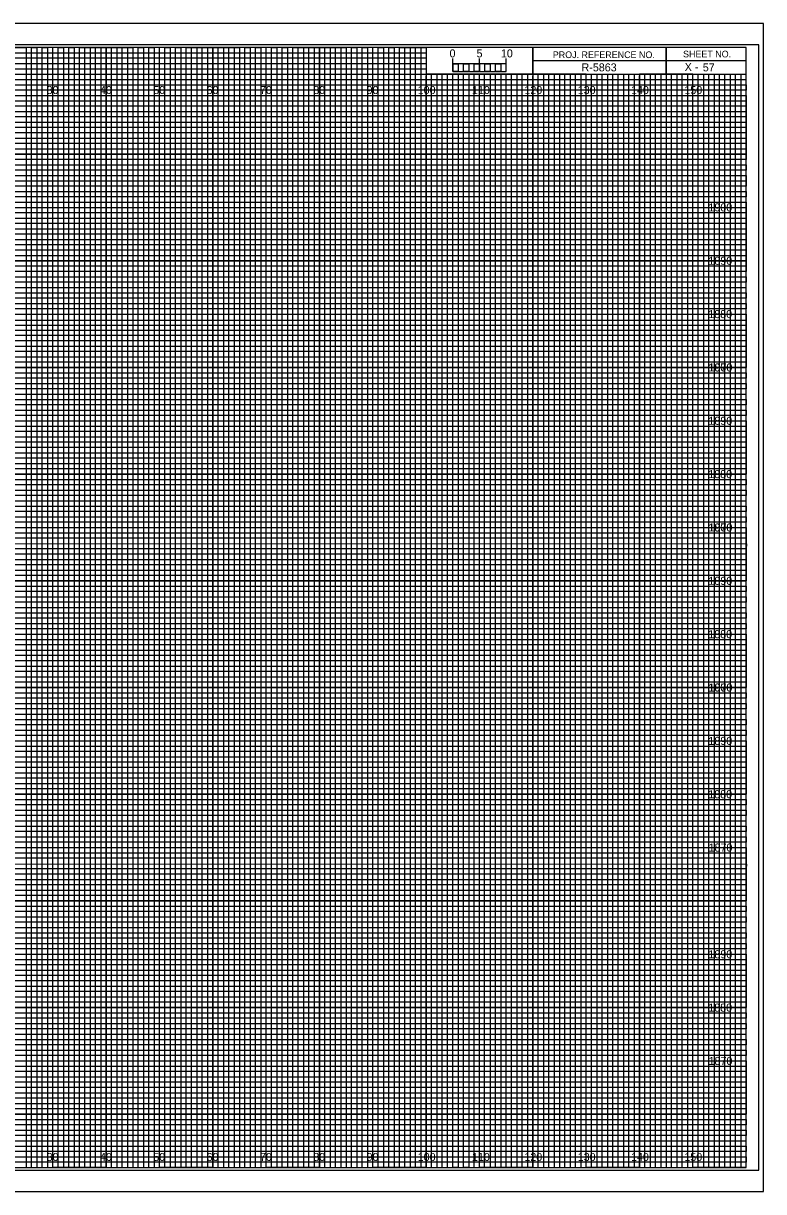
# Model space of a CAD drawing. Extents: x -13 to 323, y -4 to 214.
# Drawn here: x 184.5 to 323.3, y -4.5 to 214.5 of the extents above; entities that cross this region are included whole.
import ezdxf

# ---------------------------------------------------------------- set-up
doc = ezdxf.new("R2010")
doc.units = 0
for name, color, linetype in [('Prop XS Bar Scale Labels', 7, 'Continuous'), ('Prop XS Elevation Labels', 7, 'Continuous'), ('Prop XS Offset Labels', 7, 'Continuous'), ('Prop XS Project Number', 7, 'Continuous'), ('Prop XS Sheet Number', 7, 'Continuous'), ('Sheet Cross Section CELL', 7, 'Continuous'), ('Sheet Cross Section Grid Major CELL', 7, 'Continuous'), ('Sheet Cross Section Grid Middle CELL', 7, 'Continuous'), ('Sheet Cross Section Grid Minor 1 CELL', 7, 'Continuous'), ('Sheet Cross Section Grid Minor 2 CELL', 7, 'Continuous'), ('Sheet Cross Section Scale CELL', 7, 'Continuous'), ('Sheet Cutting Line CELL', 7, 'Continuous'), ('Sheet DOT Grid CELL', 7, 'Continuous'), ('Sheet Plot Border Inside CELL', 7, 'Continuous'), ('Sheet Plot Border Outside CELL', 7, 'Continuous')]:
    doc.layers.add(name, color=color, linetype=linetype)

msp = doc.modelspace()

# ---------------------------------------------------------------- linework, layer by layer
at = {"layer": 'Sheet Cross Section CELL'}
for p, q in [((305, 210), (305, 205)), ((305, 205), (305, 210)), ((280, 207.5), (280, 205)), ((320, 207.49), (280, 207.49)), ((280, 205), (320, 205))]:
    msp.add_line(p, q, dxfattribs=at)
for points in [[(320, 210), (0, 210), (0, 0), (320, 0)], [(280, 210), (260, 210), (260, 205.03), (280, 205.03)], [(320, 210), (280, 210), (280, 205), (320, 205)]]:
    msp.add_lwpolyline(points, close=True, dxfattribs=at)
at = {"layer": 'Sheet Cross Section Grid Major CELL'}
for p, q in [((190, 210), (180, 210)), ((190, 0), (190, 210)), ((210, 210), (200, 210)), ((200, 210), (200, 0)), ((210, 0), (210, 210)), ((230, 210), (220, 210)), ((220, 210), (220, 0)), ((230, 0), (230, 210)), ((250, 210), (240, 210)), ((240, 210), (240, 0)), ((250, 0), (250, 210)), ((260, 210), (260, 0)), ((270, 0), (270, 205)), ((290, 205), (280, 205)), ((280, 205), (280, 0)), ((290, 0), (290, 205)), ((310, 205), (300, 205)), ((300, 205), (300, 0)), ((310, 0), (310, 205)), ((200, 0), (190, 0)), ((220, 0), (210, 0)), ((240, 0), (230, 0)), ((260, 0), (250, 0)), ((280, 0), (270, 0)), ((300, 0), (290, 0)), ((320, 0), (310, 0)), ((320, 0), (320, 0))]:
    msp.add_line(p, q, dxfattribs=at)
for points in [[(0, 200), (320, 200), (320, 190), (0, 190)], [(0, 180), (320, 180), (320, 170), (0, 170)], [(0, 160), (320, 160), (320, 150), (0, 150)], [(0, 140), (320, 140), (320, 130), (0, 130)], [(0, 120), (320, 120), (320, 110), (0, 110)], [(0, 100), (320, 100), (320, 90), (0, 90)], [(0, 80), (320, 80), (320, 70), (0, 70)], [(0, 60), (320, 60), (320, 50), (0, 50)], [(0, 40), (320, 40), (320, 30), (0, 30)], [(0, 20), (320, 20), (320, 10), (0, 10)]]:
    msp.add_lwpolyline(points, dxfattribs=at)
at = {"layer": 'Sheet Cross Section Grid Middle CELL'}
for points in [[(175, 210), (185, 210), (185, 0), (195, 0), (195, 210), (205, 210), (205, 0), (215, 0), (215, 210), (225, 210), (225, 0), (235, 0), (235, 210), (245, 210), (245, 0), (255, 0), (255, 210), (259.93, 210), (260, 210), (260, 205), (264.99, 205), (264.99, 0), (275, 0), (275, 205), (285, 205), (285, 0), (295, 0), (295, 205), (305, 205), (305, 0), (315, 0), (315, 205)], [(0, 205), (275, 205)], [(0, 185), (320, 185), (320, 195), (0, 195)], [(0, 165), (320, 165), (320, 175), (0, 175)], [(0, 145), (320, 145), (320, 155), (0, 155)], [(0, 125), (320, 125), (320, 135), (0, 135)], [(0, 105), (320, 105), (320, 115), (0, 115)], [(0, 85), (320, 85), (320, 95), (0, 95)], [(0, 65), (320, 65), (320, 75), (0, 75)], [(0, 45), (320, 45), (320, 55), (0, 55)], [(0, 25), (320, 25), (320, 35), (0, 35)], [(0, 5), (320, 5), (320, 15), (0, 15)]]:
    msp.add_lwpolyline(points, dxfattribs=at)
at = {"layer": 'Sheet Cross Section Grid Minor 1 CELL'}
for p, q in [((0, 209), (260, 209)), ((260, 209), (260, 207.98)), ((260, 207.98), (0, 207.98)), ((0, 207), (260, 207)), ((260, 205.89), (0, 205.89)), ((260, 207), (260, 205.89)), ((0, 204), (320, 204))]:
    msp.add_line(p, q, dxfattribs=at)
for points in [[(0, 203), (270, 203), (320, 203), (320, 202), (0, 202)], [(0, 201), (320, 201), (320, 199), (0, 199)], [(0, 198), (320, 198), (320, 197), (0, 196.98)], [(0, 196), (320, 196), (320, 194), (0, 194)], [(0, 193), (320, 193), (320, 192), (0, 192)], [(0, 191), (320, 191), (320, 189), (0, 189)], [(0, 188), (320, 188), (320, 187), (0, 187)], [(0, 186), (320, 186), (320, 184), (0, 184)], [(0, 183), (320, 183), (320, 182), (0, 182)], [(0, 181), (320, 181), (320, 179), (0, 179)], [(0, 178), (320, 178), (320, 177), (0, 177)], [(0, 176), (320, 176), (320, 173.95), (320, 173), (320, 172), (0, 172)], [(0, 174), (320, 174), (320, 173), (0, 173)], [(0, 171), (320, 171), (320, 169), (0, 169.03)], [(0, 169.03), (320, 169), (320, 168), (0, 168)], [(0, 167), (320, 167), (320, 166), (0, 166)], [(0, 164), (320, 164), (320, 163), (0, 163)], [(0, 162), (320, 162), (320, 161), (0, 161)], [(-0.07, 158.89), (320, 158.89), (320, 157.88), (-0.07, 157.88)], [(0, 157), (320, 157), (320, 156), (0, 156)], [(0, 154), (320, 154), (320, 153), (0, 153)], [(0, 152), (320, 152), (320, 151), (0, 151)], [(0, 149), (320, 149), (320, 148), (0, 148)], [(0, 147), (320, 147), (320, 146), (0, 146)], [(0, 144), (320, 144), (320, 143), (0, 143)], [(0, 142), (320, 142), (320, 141), (0, 141)], [(0, 139), (320, 139), (319.99, 137.98), (0, 138)], [(0, 137), (320, 137), (320, 136), (0, 136)], [(0, 134), (320, 134), (320, 133), (0, 133)], [(0, 132), (320, 132), (320, 131), (0, 131)], [(0, 129), (320, 129), (320, 128), (0, 128)], [(0, 127), (320, 127), (320, 126), (0, 126)], [(0, 124), (320, 124), (320, 123), (0, 123)], [(0, 122), (320, 122), (320, 121), (0, 121)], [(0, 119), (320, 119), (320, 118), (0, 118)], [(0, 116.99), (320.07, 116.91), (320, 116), (0, 116)], [(0, 114), (320, 114), (320, 113), (0, 113)], [(0, 112), (320, 112), (320, 111), (0, 111)], [(0, 109), (320, 109), (320, 108), (0, 108)], [(0, 107), (320, 107), (320, 106), (0, 106)], [(0, 104), (320, 104), (320, 103), (0, 103)], [(0, 102), (320, 102), (320, 101), (0, 101)], [(0, 99), (320, 99), (320, 98), (0, 98)], [(0, 97), (320, 97), (320, 96), (0, 96)], [(0, 94), (320, 94), (320, 93), (0, 93)], [(0, 92), (320, 92), (320, 91), (0, 91)], [(0, 89), (320, 89), (320, 88), (0, 88)], [(0, 87), (320, 87), (320, 86), (0, 86)], [(0, 84), (320, 84), (320, 83), (0, 83)], [(0, 82), (320, 82), (320, 81), (0, 81)], [(0, 79), (320, 79), (319.99, 77.98), (0, 78)], [(0, 77), (320, 77), (320, 76), (0, 76)], [(0, 74), (320, 74), (320, 73), (0, 73)], [(0, 72), (320, 72), (320, 71), (0, 71)], [(0, 69), (320, 69), (320, 68), (0, 68)], [(0, 67), (320, 67), (320, 66), (0, 66)], [(0, 64), (320, 64), (320, 63), (0, 63)], [(0, 62), (320, 62), (320, 61), (0, 61)], [(0, 59), (320, 59), (320, 58), (0, 58)], [(0, 56.99), (320.07, 56.91), (320, 56), (0, 56)], [(0, 54), (320, 54), (320, 53), (0, 53)], [(0, 52), (320, 52), (320, 51), (0, 51)], [(0, 49), (320, 49), (320, 48), (0, 48)], [(0, 47), (320, 47), (320, 46), (0, 46)], [(0, 44), (320, 44), (320, 43), (0, 43)], [(0, 42), (320, 42), (320, 41), (0, 41)], [(0, 39), (320, 39), (320, 38), (0, 38)], [(0, 37), (320, 37), (320, 36), (0, 36)], [(0, 34), (320, 34), (320, 33), (0, 33)], [(0, 32), (320, 32), (320, 31), (0, 31)], [(0, 29), (320, 29), (320, 28), (0, 28)], [(0, 27), (320, 27), (320, 26), (0, 26)], [(0, 24), (320, 24), (320, 23), (0, 23)], [(0, 22), (320, 22), (320, 21), (0, 21)], [(0, 19), (320, 19), (320, 18), (0, 18)], [(0, 17), (320, 17), (320, 16), (0, 16)], [(0, 14), (320, 14), (320, 13), (0, 13)], [(0, 12), (320, 12), (320, 11), (0, 11)], [(0, 9), (320, 9), (320, 8), (0, 8)], [(0, 7), (320, 7), (320, 6), (0, 6)], [(0, 4), (320, 4), (320, 3), (0, 3)], [(0, 2), (320, 2), (320, 1), (0, 1)]]:
    msp.add_lwpolyline(points, dxfattribs=at)
at = {"layer": 'Sheet Cross Section Grid Minor 2 CELL'}
for p, q in [((267, 205), (266.01, 205)), ((266.01, 205), (266.01, 0)), ((267, 0), (267, 205)), ((269, 205), (268, 205)), ((268, 205), (268, 0)), ((269, 0), (269, 205)), ((266.01, 0), (265, 0)), ((268, 0), (267, 0))]:
    msp.add_line(p, q, dxfattribs=at)
for points in [[(185, 0), (186, 0), (186, 210), (187, 210), (187, 0)], [(187, 0), (188, 0), (188, 210), (189, 210), (189, 0)], [(190, 0), (191, 0), (191, 210), (192, 210), (192, 0)], [(192, 0), (193, 0), (193, 210), (194, 210), (194, 0)], [(195, 0), (196, 0), (196, 210), (197, 210), (197, 0)], [(197, 0), (198, 0), (198, 210), (199, 210), (199, 0)], [(200, 0), (201, 0), (201, 210), (202, 210), (202, 0)], [(202, 0), (203, 0), (203, 210), (204, 210), (204, 0)], [(205, 0), (206, 0), (206, 210), (207, 210), (207, 0)], [(207, 0), (208, 0), (208, 210), (209, 210), (209, 0)], [(210, 0), (211, 0), (211, 210), (212, 210), (212, 0)], [(212, 0), (213, 0), (213, 210), (214, 210), (214, 0)], [(215, 0), (216, 0), (216, 210), (217, 210), (217, 0)], [(217, 0), (218, 0), (218, 210), (219, 210), (219, 0)], [(220, 0), (221, 0), (221, 210), (222, 210), (222, 0)], [(222, 0), (223, 0), (223, 210), (224, 210), (224, 0)], [(225, 0), (226, 0), (226, 210), (227, 210), (227, 0)], [(227, 0), (228, 0), (228, 210), (229, 210), (229, 0)], [(230, 0), (231, 0), (231, 210), (232, 210), (232, 0)], [(232, 0), (233, 0), (233, 210), (234, 210), (234, 0)], [(235, 0), (236, 0), (236, 210), (237, 210), (237, 0)], [(237, 0), (238, 0), (238, 210), (239, 210), (239, 0)], [(240, 0), (241, 0), (241, 210), (242, 210), (242, 0)], [(242, 0), (243, 0), (243, 210), (244, 210), (244, 0)], [(245, 0), (246, 0), (246, 210), (247, 210), (247, 0)], [(247, 0), (248, 0), (248, 210), (249, 210), (249, 0)], [(250, 0), (251, 0), (251, 210), (252, 210), (252, 0)], [(252, 0), (253, 0), (253, 210), (254, 210), (254, 0)], [(255, 0), (256, 0), (256, 210), (257, 210), (257, 0)], [(257, 0), (258, 0), (258, 210), (259, 210), (259, 0)], [(260, 0), (261, 0), (261, 205), (262.02, 205), (262.02, 0)], [(262, 0), (263, 0), (263, 205), (263.99, 205), (263.99, 0)], [(270, 0), (270.98, 0), (270.98, 205), (272, 205), (272, 0)], [(272, 0), (273, 0), (273, 205), (274.05, 205), (274.05, 0)], [(275, 0), (276, 0), (276, 205), (277, 205), (277, 0)], [(277, 0), (278, 0), (278, 205), (279, 205), (279, 0)], [(280, 0), (281, 0), (281, 205), (282, 205), (282, 0)], [(282, 0), (283, 0), (283, 205), (284, 205), (284, 0)], [(285, 0), (286, 0), (286, 205), (287, 205), (287, 0)], [(287, 0), (288, 0), (288, 205), (289, 205), (289, 0)], [(290, 0), (291, 0), (291, 205), (292, 205), (292, 0)], [(292, 0), (293, 0), (293, 205), (294, 205), (294, 0)], [(295, 0), (296, 0), (296, 205), (297, 205), (297, 0)], [(297, 0), (298, 0), (298, 205), (299, 205), (299, 0)], [(300, 0), (301, 0), (301, 205), (302, 205), (302, 0)], [(302, 0), (303, 0), (303, 205), (304, 205), (304, 0)], [(305, 0), (306, 0), (306, 205), (307, 205), (307, 0)], [(307, 0), (308, 0), (308, 205), (309, 205), (309, 0)], [(310, 0), (311, 0), (311, 205), (312, 205), (312, 0)], [(312, 0), (313, 0), (313, 205), (314, 205), (314, 0)], [(315, 0), (316, 0), (316, 205), (317, 205), (317, 0)], [(317, 0), (318, 0), (318, 205), (319, 205), (319, 0)]]:
    msp.add_lwpolyline(points, dxfattribs=at)
at = {"layer": 'Sheet Cross Section Scale CELL'}
for p, q in [((265, 205.49), (265, 207.9)), ((265, 206.9), (265, 207.9)), ((270, 205.49), (270, 207.9)), ((275, 205.49), (275, 207.9)), ((275, 206.9), (275, 207.9))]:
    msp.add_line(p, q, dxfattribs=at)
for points in [[(275, 206.9), (265, 206.9), (265, 205.49), (275, 205.49)], [(265, 206.9), (266, 206.9), (266, 205.49), (265, 205.49)], [(267, 206.9), (268, 206.9), (268, 205.49), (267, 205.49)], [(269, 206.9), (270, 206.9), (270, 205.49), (269, 205.49)], [(271, 206.9), (272, 206.9), (272, 205.49), (271, 205.49)], [(273, 206.9), (274, 206.9), (274, 205.49), (273, 205.49)]]:
    msp.add_lwpolyline(points, close=True, dxfattribs=at)
at = {"layer": 'Sheet Cutting Line CELL'}
for p, q in [((323.3, 214.5), (-13.4, 214.5)), ((-13.4, -4.5), (323.3, -4.5))]:
    msp.add_line(p, q, dxfattribs=at)
at = {"layer": 'Sheet DOT Grid CELL'}
for p, q in [((190, 0), (190, 210)), ((200, 0), (200, 210)), ((210, 0), (210, 210)), ((220, 0), (220, 210)), ((230, 0), (230, 210)), ((240, 0), (240, 210)), ((250, 0), (250, 210)), ((260, 0), (260, 204.69)), ((270, 0), (270, 204.69)), ((280, 0), (280, 204.69)), ((290, 0), (290, 204.69)), ((300, 0), (300, 204.69)), ((310, 0), (310, 204.69)), ((0, 200), (320, 200)), ((0, 190), (320, 190)), ((0, 180), (320, 180)), ((0, 170), (320, 170)), ((0, 160), (320, 160)), ((0, 150), (320, 150)), ((0, 140), (320, 140)), ((0, 130), (320, 130)), ((0, 120), (320, 120)), ((0, 110), (320, 110)), ((0, 100), (320, 100)), ((0, 90), (320, 90)), ((0, 80), (320, 80)), ((0, 70), (320, 70)), ((0, 60), (320, 60)), ((0, 50), (320, 50)), ((0, 40), (320, 40)), ((0, 30), (320, 30)), ((0, 20), (320, 20)), ((0, 10), (320, 10))]:
    msp.add_line(p, q, dxfattribs=at)
at = {"layer": 'Sheet Plot Border Inside CELL'}
msp.add_lwpolyline([(-10.8, -0.5), (322.4, -0.5), (322.4, 210.5), (-10.8, 210.5)], close=True, dxfattribs=at)
at = {"layer": 'Sheet Plot Border Outside CELL'}
msp.add_lwpolyline([(-13.4, -4.5), (323.3, -4.5), (323.3, 214.5), (-13.4, 214.5)], close=True, dxfattribs=at)

# ---------------------------------------------------------------- texts
at = {"layer": 'Prop XS Bar Scale Labels'}
for s, p in [('5', (269.47, 208.12)), ('10', (274.04, 208.12))]:
    msp.add_text(s, height=1.5, dxfattribs=at).set_placement(p)
at = {"layer": 'Prop XS Elevation Labels'}
for s, p in [('1900', (312.95, 179.25)), ('1890', (312.95, 169.25)), ('1880', (312.92, 159.25)), ('1900', (312.95, 149.25)), ('1870', (312.98, 149.25)), ('1890', (312.95, 139.25)), ('1880', (312.92, 129.25)), ('1900', (312.95, 119.25)), ('1870', (312.98, 119.25)), ('1890', (312.95, 109.25)), ('1880', (312.92, 99.25)), ('1900', (312.95, 89.25)), ('1870', (312.98, 89.25)), ('1890', (312.95, 79.25)), ('1880', (312.92, 69.25)), ('1870', (312.98, 59.25)), ('1890', (312.95, 39.25)), ('1880', (312.92, 29.25)), ('1870', (312.98, 19.25))]:
    msp.add_text(s, height=1.5, dxfattribs=at).set_placement(p)
at = {"layer": 'Prop XS Offset Labels'}
for s, p in [('30', (188.86, 201.25)), ('40', (198.86, 201.25)), ('50', (208.86, 201.25)), ('60', (218.86, 201.25)), ('70', (228.86, 201.25)), ('80', (238.86, 201.25)), ('90', (248.86, 201.25)), ('100', (258.44, 201.25)), ('110', (268.62, 201.25)), ('120', (278.44, 201.25)), ('130', (288.44, 201.25)), ('140', (298.44, 201.25)), ('150', (308.44, 201.25)), ('30', (188.86, 1.25)), ('40', (198.86, 1.25)), ('50', (208.86, 1.25)), ('60', (218.86, 1.25)), ('70', (228.86, 1.25)), ('80', (238.86, 1.25)), ('90', (248.86, 1.25)), ('100', (258.44, 1.25)), ('110', (268.62, 1.25)), ('120', (278.44, 1.25)), ('130', (288.44, 1.25)), ('140', (298.44, 1.25)), ('150', (308.44, 1.25))]:
    msp.add_text(s, height=1.5, dxfattribs=at).set_placement(p)
at = {"layer": 'Prop XS Project Number'}
msp.add_text('R-5863', height=1.5, dxfattribs=at).set_placement((289.16, 205.5))
at = {"layer": 'Prop XS Sheet Number'}
msp.add_text('57', height=1.5, dxfattribs=at).set_placement((311.89, 205.5))
at = {"layer": 'Sheet Cross Section CELL'}
for s, height, p in [('PROJ. REFERENCE NO.', 1.25, (283.77, 207.99)), ('SHEET NO.', 1.25, (308.19, 208.12)), ('X -    ', 1.5, (308.5, 205.58))]:
    msp.add_text(s, height=height, dxfattribs=at).set_placement(p)
at = {"layer": 'Sheet Cross Section Scale CELL'}
msp.add_text('0', height=1.5, dxfattribs=at).set_placement((264.41, 208.12))

doc.saveas('drawing.dxf')
